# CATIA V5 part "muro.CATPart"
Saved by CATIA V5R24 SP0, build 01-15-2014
Part number: muro
Bounding box of the stored display mesh (mm): x 0 to 3, y -60 to 60, z -223.5 to 223.5
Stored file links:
  C:\Users\Fatec\Desktop\Maquina componentes catia\muro.CATPart
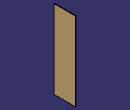
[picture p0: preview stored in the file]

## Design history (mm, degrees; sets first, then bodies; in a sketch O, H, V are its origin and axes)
Body1 (main body)
  Sketch1 on yz-plane, origin (0, 0, 0), H (0, 1, 0), V (0, 0, 1)
    line L1 (-60, 223.5) -> (60, 223.5)
    line L2 (60, 223.5) -> (60, -223.5)
    line L3 (60, -223.5) -> (-60, -223.5)
    line L4 (-60, -223.5) -> (-60, 223.5)
    length L3 = 120
    length L2 = 447
    horizontal: L1 H, L3 H
    vertical: L2 V, L4 V
    symmetry: L4 L2 V, L3 L1 H
  Pad1: profile Sketch1, direction (1, 0, 0), length 3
